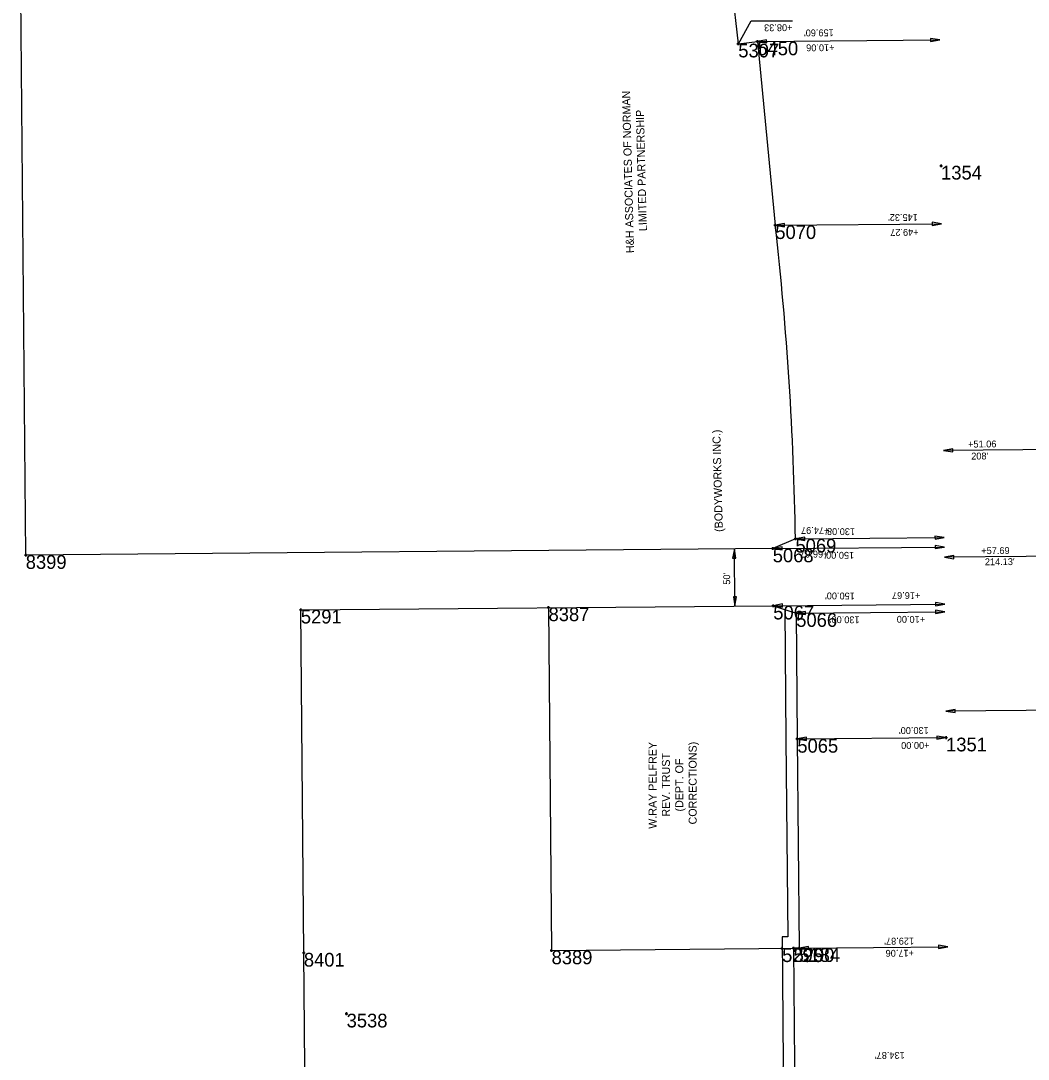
# Model space of a CAD drawing. Extents: x 2145146 to 2158053, y 137507 to 150829.
# Drawn here: x 2150029 to 2150909, y 141238 to 142146 of the extents above; entities that cross this region are included whole.
import ezdxf

# ---------------------------------------------------------------- set-up
doc = ezdxf.new("R2010")
doc.units = 0
for name, color, linetype in [('ALIGN_Cogo Points', 7, 'Continuous'), ('ALIGN_ROW Dimension', 7, 'Continuous'), ('ALIGN_ROW Line', 7, 'Continuous'), ('PLSS_Easement', 7, 'Continuous'), ('PLSS_Property Line', 7, 'Continuous'), ('PLSS_Text_TURNED OFF', 7, 'Continuous')]:
    doc.layers.add(name, color=color, linetype=linetype)

# ---------------------------------------------------------------- blocks, each defined once
blk = doc.blocks.new('Arrowhd')
at = {"layer": 'PLSS_Property Line'}
blk.add_lwpolyline([(0.125, -0.021), (0.125, 0.021), (0, 0)], close=True, dxfattribs=at)

msp = doc.modelspace()

# ---------------------------------------------------------------- linework, layer by layer
at = {"layer": 'ALIGN_Cogo Points'}
for points in [[(2150656.03, 142126.03), (2150656.03, 142127.23), (2150656.03, 142126.03), (2150654.83, 142126.03), (2150656.03, 142126.03), (2150656.03, 142124.83), (2150656.03, 142126.03), (2150657.23, 142126.03)], [(2150672.68, 142127.91), (2150672.68, 142129.11), (2150672.68, 142127.91), (2150671.48, 142127.91), (2150672.68, 142127.91), (2150672.68, 142126.71), (2150672.68, 142127.91), (2150673.88, 142127.91)], [(2150833.24, 142019.25), (2150833.24, 142020.45), (2150833.24, 142019.25), (2150832.04, 142019.25), (2150833.24, 142019.25), (2150833.24, 142018.05), (2150833.24, 142019.25), (2150834.44, 142019.25)], [(2150688.37, 141967.25), (2150688.37, 141968.45), (2150688.37, 141967.25), (2150687.17, 141967.25), (2150688.37, 141967.25), (2150688.37, 141966.05), (2150688.37, 141967.25), (2150689.57, 141967.25)], [(2150706.01, 141693.09), (2150706.01, 141694.29), (2150706.01, 141693.09), (2150704.81, 141693.09), (2150706.01, 141693.09), (2150706.01, 141691.89), (2150706.01, 141693.09), (2150707.21, 141693.09)], [(2150033.29, 141678.82), (2150033.29, 141680.02), (2150033.29, 141678.82), (2150032.09, 141678.82), (2150033.29, 141678.82), (2150033.29, 141677.62), (2150033.29, 141678.82), (2150034.49, 141678.82)], [(2150686.16, 141684.61), (2150686.16, 141685.81), (2150686.16, 141684.61), (2150684.96, 141684.61), (2150686.16, 141684.61), (2150686.16, 141683.41), (2150686.16, 141684.61), (2150687.36, 141684.61)], [(2150273.72, 141631.09), (2150273.72, 141632.29), (2150273.72, 141631.09), (2150272.52, 141631.09), (2150273.72, 141631.09), (2150273.72, 141629.89), (2150273.72, 141631.09), (2150274.92, 141631.09)], [(2150490.21, 141633.14), (2150490.21, 141634.34), (2150490.21, 141633.14), (2150489.01, 141633.14), (2150490.21, 141633.14), (2150490.21, 141631.94), (2150490.21, 141633.14), (2150491.41, 141633.14)], [(2150686.6, 141634.62), (2150686.6, 141635.82), (2150686.6, 141634.62), (2150685.4, 141634.62), (2150686.6, 141634.62), (2150686.6, 141633.42), (2150686.6, 141634.62), (2150687.8, 141634.62)], [(2150706.66, 141628.13), (2150706.66, 141629.33), (2150706.66, 141628.13), (2150705.46, 141628.13), (2150706.66, 141628.13), (2150706.66, 141626.93), (2150706.66, 141628.13), (2150707.86, 141628.13)], [(2150707.62, 141518.13), (2150707.62, 141519.33), (2150707.62, 141518.13), (2150706.42, 141518.13), (2150707.62, 141518.13), (2150707.62, 141516.93), (2150707.62, 141518.13), (2150708.82, 141518.13)], [(2150837.61, 141519.27), (2150837.61, 141520.47), (2150837.61, 141519.27), (2150836.41, 141519.27), (2150837.61, 141519.27), (2150837.61, 141518.07), (2150837.61, 141519.27), (2150838.81, 141519.27)], [(2150276.37, 141331.1), (2150276.37, 141332.3), (2150276.37, 141331.1), (2150275.17, 141331.1), (2150276.37, 141331.1), (2150276.37, 141329.9), (2150276.37, 141331.1), (2150277.57, 141331.1)], [(2150492.86, 141333.15), (2150492.86, 141334.35), (2150492.86, 141333.15), (2150491.66, 141333.15), (2150492.86, 141333.15), (2150492.86, 141331.95), (2150492.86, 141333.15), (2150494.06, 141333.15)], [(2150694.35, 141335.06), (2150694.35, 141336.26), (2150694.35, 141335.06), (2150693.15, 141335.06), (2150694.35, 141335.06), (2150694.35, 141333.86), (2150694.35, 141335.06), (2150695.55, 141335.06)], [(2150704.35, 141335.15), (2150704.35, 141336.35), (2150704.35, 141335.15), (2150703.15, 141335.15), (2150704.35, 141335.15), (2150704.35, 141333.95), (2150704.35, 141335.15), (2150705.55, 141335.15)], [(2150709.35, 141335.2), (2150709.35, 141336.4), (2150709.35, 141335.2), (2150708.15, 141335.2), (2150709.35, 141335.2), (2150709.35, 141334), (2150709.35, 141335.2), (2150710.55, 141335.2)], [(2150313.73, 141277.91), (2150313.73, 141279.11), (2150313.73, 141277.91), (2150312.53, 141277.91), (2150313.73, 141277.91), (2150313.73, 141276.71), (2150313.73, 141277.91), (2150314.93, 141277.91)]]:
    msp.add_lwpolyline(points, dxfattribs=at)
at = {"layer": 'ALIGN_ROW Dimension'}
for points in [[(2150656.1, 142126.03), (2150667.37, 142145.98), (2150703.3, 142146.04)], [(2150672.67, 142127.89), (2150832.27, 142129.29)], [(2150688.37, 141967.25), (2150833.68, 141968.52)], [(2151043.41, 141772.14), (2150835.42, 141770.32)], [(2150705.94, 141693.06), (2150836.08, 141694.2)], [(2150653.14, 141634.34), (2150652.7, 141684.32)], [(2150686.16, 141684.61), (2150836.16, 141685.93)], [(2151050.36, 141678.83), (2150836.23, 141676.95)], [(2150686.6, 141634.62), (2150836.59, 141635.93)], [(2150706.66, 141628.13), (2150836.65, 141629.27)], [(2151082.77, 141544.53), (2150837.41, 141542.38)], [(2150707.61, 141518.13), (2150837.61, 141519.26)], [(2150709.34, 141335.19), (2150839.22, 141336.33)]]:
    msp.add_lwpolyline(points, dxfattribs=at)
at = {"layer": 'ALIGN_ROW Line'}
for points in [[(2150631.53, 142295.02), (2150631.53, 142295.02), (2150668.09, 142174.84), (2150650.4, 142174.68), (2150656.03, 142126.03), (2150672.68, 142127.91), (2150688.37, 141967.25)], [(2150706.01, 141693.09), (2150686.16, 141684.61), (2150033.29, 141678.82)], [(2150273.72, 141631.09), (2150686.6, 141634.62), (2150706.66, 141628.13), (2150707.62, 141518.13), (2150709.35, 141335.2), (2150704.35, 141335.15), (2150705.24, 141233.86), (2150693.6, 141035.03), (2150673.39, 140680.22), (2150658.77, 140421.03), (2150632.34, 140395.87), (2150465.99, 140394.26), (2150394.65, 140393.58), (2150194.75, 140391.64), (2150194.84, 140381.64)]]:
    msp.add_lwpolyline(points, dxfattribs=at)
msp.add_arc((2147849.59, 141646.93), 2856.79, 0.92584, 6.43789, dxfattribs=at)
at = {"layer": 'PLSS_Easement'}
msp.add_lwpolyline([(2150696.63, 141631.37), (2150697.62, 141518.05), (2150699.26, 141345.1), (2150694.26, 141345.05), (2150695.24, 141234.11), (2150683.62, 141035.61), (2150683.58, 141034.94)], dxfattribs=at)
at = {"layer": 'PLSS_Property Line'}
for points in [[(2150033.29, 141678.82), (2150028.96, 142168.8)], [(2150490.17, 141633.16), (2150492.86, 141333.15), (2150704.35, 141335.15)], [(2150389.01, 141032.16), (2150279.02, 141031.11), (2150276.37, 141331.1), (2150273.72, 141631.09)]]:
    msp.add_lwpolyline(points, dxfattribs=at)

# ---------------------------------------------------------------- block references
at = {"layer": 'ALIGN_ROW Dimension'}
for p, xscale, yscale, rotation in [((2150672.7, 142127.89), 65.00000000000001, 65, 0.7805293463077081), ((2150832.22, 142129.31), 65, 65, 180), ((2150688.38, 141967.25), 65.00000000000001, 65, 0.7805293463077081), ((2150833.62, 141968.55), 65, 65, 180), ((2150835.4, 141770.32), 65.00000000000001, 65, 0.7805293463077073), ((2150836.07, 141694.2), 65, 65, -179.23112075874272), ((2150706, 141693.08), 65, 65.00000000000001, 0.4451922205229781), ((2150836.1, 141685.95), 65, 65, 180), ((2150652.7, 141684.32), 65, 64.99999999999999, -91.83689220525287), ((2150686.18, 141684.6), 65.00000000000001, 65, 0.7805293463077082), ((2150836.23, 141676.95), 65.00000000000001, 65, 0.7805293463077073), ((2150653.14, 141634.34), 65, 64.99999999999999, 90.50853156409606), ((2150686.57, 141634.66), 65.00000000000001, 65, 0.7805293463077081), ((2150836.53, 141635.95), 65, 65, 180), ((2150706.67, 141628.12), 65.00000000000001, 65, 0.7805293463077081), ((2150836.59, 141629.29), 65, 65, 180), ((2150837.39, 141542.38), 65.00000000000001, 65, 0.7805293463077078), ((2150707.63, 141518.13), 65.00000000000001, 65, 0.7805293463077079), ((2150837.56, 141519.29), 65, 65, 180), ((2150709.36, 141335.2), 65.00000000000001, 65, 0.7805293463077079), ((2150839.16, 141336.35), 65, 65, 180)]:
    msp.add_blockref('Arrowhd', p, dxfattribs=dict(at, xscale=xscale, yscale=yscale, rotation=rotation))

# ---------------------------------------------------------------- texts
at = {"layer": 'ALIGN_Cogo Points'}
for s, p in [('5307', (2150656.03, 142114.03)), ('5450', (2150672.68, 142115.91)), ('1354', (2150833.24, 142007.25)), ('5070', (2150688.37, 141955.25)), ('5069', (2150706.01, 141681.09)), ('8399', (2150033.29, 141666.82)), ('5068', (2150686.16, 141672.61)), ('8387', (2150490.21, 141621.14)), ('5067', (2150686.6, 141622.62)), ('5291', (2150273.72, 141619.09)), ('5066', (2150706.66, 141616.13)), ('5065', (2150707.62, 141506.13)), ('1351', (2150837.61, 141507.27)), ('8389', (2150492.86, 141321.15)), ('5296', (2150694.35, 141323.06)), ('5290', (2150704.35, 141323.15)), ('5184', (2150709.35, 141323.2)), ('8401', (2150276.37, 141319.1)), ('3538', (2150313.73, 141265.91))]:
    msp.add_text(s, height=12, dxfattribs=at).set_placement(p)
at = {"layer": 'ALIGN_ROW Dimension'}
for s, rotation, p in [('+08.33', 180.3718, (2150703.35, 142143.05)), ("159.60'", 180.3718, (2150739.47, 142138.58)), ('+10.06', 180.3718, (2150740.11, 142125.53)), ("145.32'", 180.3718, (2150812.94, 141977.15)), ('+49.27', 180.3718, (2150813.58, 141964.1)), ('+51.06', 0.3718, (2150856.88, 141772.91)), ("208'", 0.3718, (2150859.61, 141762.44)), ('+74.97', 179.59675, (2150735.65, 141703.29)), ("130.08'", 179.59675, (2150758.1, 141702.32)), ('+66.67', 179.59675, (2150734.87, 141682.61)), ("150.00'", 179.59675, (2150757.32, 141681.64)), ('+57.69', 0.3718, (2150868.41, 141679.71)), ("214.13'", 0.3718, (2150871.53, 141670)), ("50'", 90.65899, (2150648.97, 141653.05)), ("150.00'", 179.59675, (2150757.91, 141646.04)), ('+16.67', 179.59675, (2150815.15, 141646.38)), ("130.00'", 179.59675, (2150762.07, 141625.27)), ('+10.00', 179.59675, (2150819.31, 141625.61)), ("130.00'", 180.3718, (2150822.47, 141528.59)), ('+00.00', 180.3718, (2150823.11, 141515.54)), ("129.87'", 180.3718, (2150809.65, 141344.39)), ('+17.06', 180.3718, (2150809.52, 141333.85)), ("134.87'", 180.3718, (2150801.49, 141244.51))]:
    msp.add_text(s, height=6, rotation=rotation, dxfattribs=at).set_placement(p)
at = {"layer": 'PLSS_Text_TURNED OFF'}
for s, rotation, p in [('H&H ASSOCIATES OF NORMAN', 91.42926, (2150564.94, 141943.02)), ('LIMITED PARTNERSHIP', 91.42926, (2150576.16, 141962.24)), ('(BODYWORKS INC.)', 91.42926, (2150642.56, 141699.24)), ('W.RAY PELFREY', 90, (2150584.59, 141439.58)), ('CORRECTIONS)', 90, (2150619.66, 141443.39)), ('REV. TRUST', 90, (2150596.28, 141450.19)), ('(DEPT. OF', 90, (2150607.97, 141454.69))]:
    msp.add_text(s, height=7, rotation=rotation, dxfattribs=at).set_placement(p)

doc.saveas('drawing.dxf')
